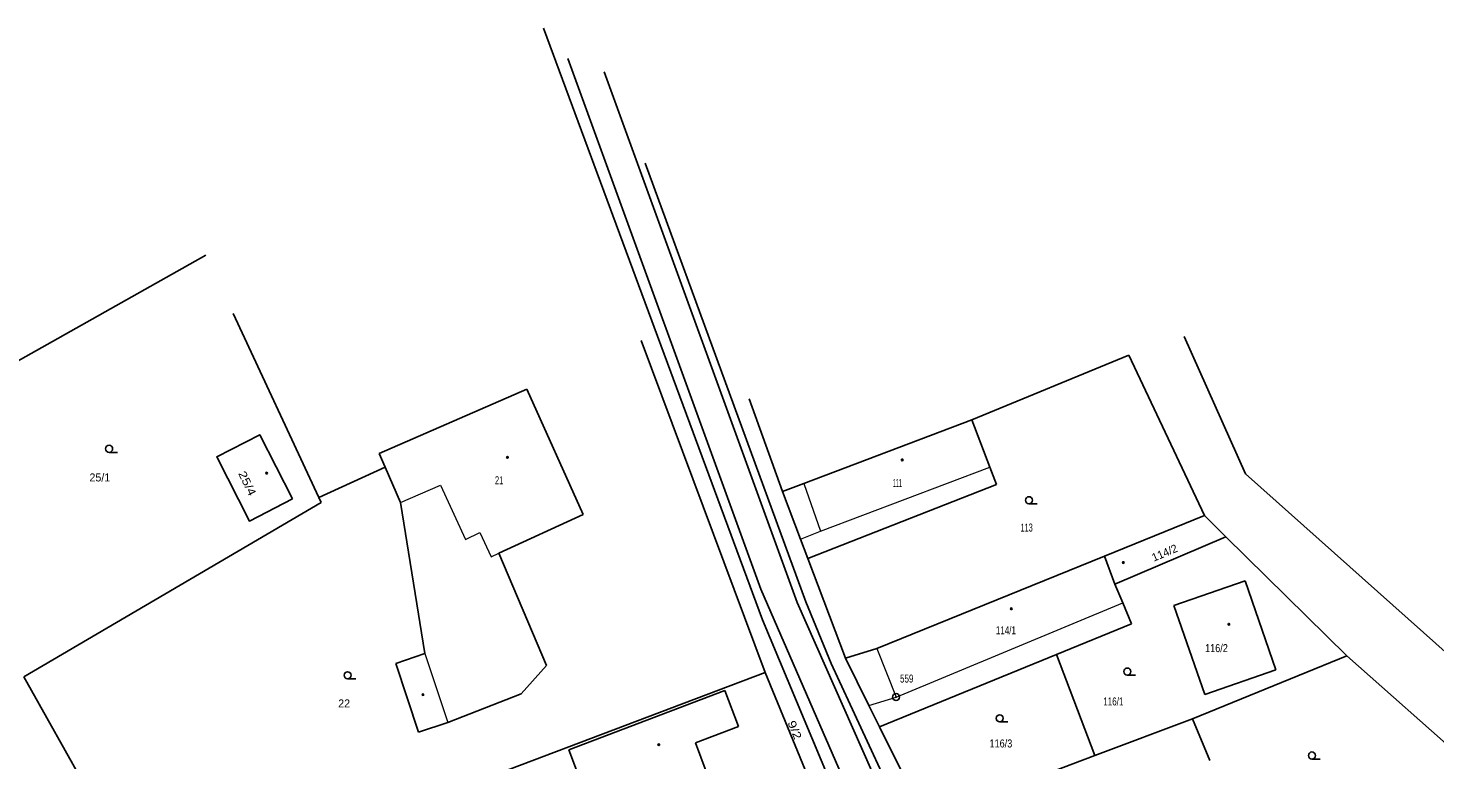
# Model space of a CAD drawing. Extents: x -592965 to -592390, y -1145071 to -1144631.
# Drawn here: x -592769.5 to -592620.1, y -1144708.7 to -1144631 of the extents above; entities that cross this region are included whole.
import ezdxf
from ezdxf.enums import TextEntityAlignment as Align

# ---------------------------------------------------------------- set-up
doc = ezdxf.new("R2010")
doc.units = 0
doc.header["$LTSCALE"] = 0.17
doc.layers.add('4', color=7, linetype='Continuous', lineweight=25)

msp = doc.modelspace()

# ---------------------------------------------------------------- linework, layer by layer
at = {"layer": '4'}
for p, q in [((-592712.14, -1144634.26), (-592691.66, -1144690.59)), ((-592708.27, -1144635.66), (-592687.79, -1144692.02)), ((-592703.94, -1144645.37), (-592686.85, -1144691.94)), ((-592784.33, -1144674.09), (-592750.58, -1144655.15)), ((-592747.69, -1144661.32), (-592738.57, -1144680.87)), ((-592704.36, -1144664.19), (-592691.2, -1144699.44)), ((-592646.68, -1144663.78), (-592640.18, -1144678.35)), ((-592669.23, -1144672.61), (-592652.56, -1144665.74)), ((-592652.56, -1144665.74), (-592644.54, -1144682.77)), ((-592732.18, -1144676.2), (-592716.5, -1144669.38)), ((-592716.5, -1144669.38), (-592710.51, -1144682.66)), ((-592692.87, -1144670.4), (-592689.34, -1144680.24)), ((-592687.08, -1144679.38), (-592669.23, -1144672.61)), ((-592669.23, -1144672.61), (-592667.32, -1144677.64)), ((-592759.985, -1144676.07), (-592760.86, -1144676.07)), ((-592732.18, -1144676.2), (-592731.54, -1144677.66)), ((-592738.57, -1144680.87), (-592731.54, -1144677.66)), ((-592731.54, -1144677.66), (-592729.92, -1144681.4)), ((-592667.32, -1144677.64), (-592666.62, -1144679.5)), ((-592640.18, -1144678.35), (-592593.65, -1144719.8)), ((-592689.34, -1144680.24), (-592687.08, -1144679.38)), ((-592686.65, -1144687.35), (-592666.62, -1144679.5)), ((-592769.91, -1144699.89), (-592738.34, -1144681.38)), ((-592738.57, -1144680.87), (-592738.34, -1144681.38)), ((-592729.92, -1144681.4), (-592727.32, -1144697.42)), ((-592689.34, -1144680.24), (-592687.43, -1144685.29)), ((-592662.295, -1144681.53), (-592663.17, -1144681.53)), ((-592719.46, -1144686.79), (-592710.51, -1144682.66)), ((-592644.54, -1144682.77), (-592642.26, -1144685.04)), ((-592687.43, -1144685.29), (-592686.65, -1144687.35)), ((-592654.03, -1144690.07), (-592642.26, -1144685.04)), ((-592642.26, -1144685.04), (-592629.42, -1144697.69)), ((-592719.46, -1144686.79), (-592714.4, -1144698.69)), ((-592686.65, -1144687.35), (-592682.65, -1144697.93)), ((-592654.03, -1144690.07), (-592655.14, -1144687.08)), ((-592691.66, -1144690.59), (-592680.91, -1144715.27)), ((-592647.77, -1144692.32), (-592640.2, -1144689.71)), ((-592640.2, -1144689.71), (-592636.94, -1144699.17)), ((-592687.79, -1144692.02), (-592678.19, -1144713.68)), ((-592686.85, -1144691.94), (-592684.18, -1144698.5)), ((-592647.77, -1144692.32), (-592644.49, -1144701.79)), ((-592730.42, -1144698.48), (-592727.32, -1144697.42)), ((-592682.65, -1144697.93), (-592679.33, -1144696.91)), ((-592660.24, -1144697.52), (-592656.17, -1144708.27)), ((-592645.8, -1144704.36), (-592629.42, -1144697.69)), ((-592629.42, -1144697.69), (-592613.93, -1144711.39)), ((-592756.36, -1144724.09), (-592691.2, -1144699.44)), ((-592730.42, -1144698.48), (-592728.01, -1144705.79)), ((-592717.08, -1144701.69), (-592714.4, -1144698.69)), ((-592684.18, -1144698.5), (-592676.33, -1144715.39)), ((-592644.49, -1144701.79), (-592636.94, -1144699.17)), ((-592769.91, -1144699.89), (-592756.36, -1144724.09)), ((-592734.655, -1144700.11), (-592735.53, -1144700.11)), ((-592651.845, -1144699.72), (-592652.72, -1144699.72)), ((-592724.87, -1144704.74), (-592717.08, -1144701.69)), ((-592712.03, -1144707.64), (-592695.45, -1144701.37)), ((-592695.45, -1144701.37), (-592694.02, -1144705.16)), ((-592728.01, -1144705.79), (-592724.87, -1144704.74)), ((-592698.59, -1144706.9), (-592694.02, -1144705.16)), ((-592665.395, -1144704.68), (-592666.27, -1144704.68)), ((-592645.8, -1144704.36), (-592643.94, -1144708.8)), ((-592698.59, -1144706.9), (-592697.44, -1144709.96)), ((-592712.03, -1144707.64), (-592709.92, -1144713.22)), ((-592632.235, -1144708.63), (-592633.11, -1144708.63))]:
    msp.add_line(p, q, dxfattribs=at)
at = {"layer": '4', "lineweight": 13}
for p, q in [((-592685.29, -1144684.43), (-592667.32, -1144677.64)), ((-592729.92, -1144681.4), (-592725.68, -1144679.54)), ((-592687.08, -1144679.38), (-592685.29, -1144684.43)), ((-592687.43, -1144685.29), (-592685.29, -1144684.43)), ((-592677.28, -1144702.05), (-592653.2, -1144692.06)), ((-592727.32, -1144697.42), (-592724.87, -1144704.74)), ((-592679.33, -1144696.91), (-592677.28, -1144702.05)), ((-592680.17, -1144702.93), (-592677.28, -1144702.05))]:
    msp.add_line(p, q, dxfattribs=at)
at = {"layer": '4'}
for points in [[(-592682.6, -1144715), (-592691.47, -1144693.85), (-592714.72, -1144631.04)], [(-592679.33, -1144696.91), (-592655.14, -1144687.08), (-592644.54, -1144682.77)], [(-592654.03, -1144690.07), (-592653.2, -1144692.06), (-592652.28, -1144694.27)], [(-592679.04, -1144705.21), (-592660.24, -1144697.52), (-592652.28, -1144694.27)], [(-592682.65, -1144697.93), (-592680.17, -1144702.93), (-592679.04, -1144705.21), (-592674.05, -1144715.26), (-592669.9, -1144713.45)], [(-592691.2, -1144699.44), (-592685.87, -1144712.37), (-592685.06, -1144715.99), (-592681.65, -1144724.59), (-592678.44, -1144732.7)], [(-592669.9, -1144713.45), (-592656.17, -1144708.27), (-592645.8, -1144704.36)]]:
    msp.add_lwpolyline(points, dxfattribs=at)
msp.add_lwpolyline([(-592741.37, -1144681.02), (-592744.86, -1144674.21), (-592749.42, -1144676.53), (-592745.95, -1144683.37)], close=True, dxfattribs=at)
at = {"layer": '4', "lineweight": 13}
for points in [[(-592725.68, -1144679.54), (-592723.01, -1144685.31), (-592721.47, -1144684.57)], [(-592721.47, -1144684.57), (-592720.27, -1144687.17), (-592719.46, -1144686.79)]]:
    msp.add_lwpolyline(points, dxfattribs=at)
at = {"layer": '4'}
for centre, radius in [((-592760.86, -1144675.695), 0.375), ((-592718.55, -1144676.6), 0.0875), ((-592676.63, -1144676.87), 0.0875), ((-592744.12, -1144678.28), 0.0875), ((-592663.17, -1144681.155), 0.375), ((-592653.14, -1144687.77), 0.0875), ((-592665.03, -1144692.68), 0.0875), ((-592641.93, -1144694.32), 0.0875), ((-592735.53, -1144699.735), 0.375), ((-592652.72, -1144699.345), 0.375), ((-592727.52, -1144701.79), 0.0875), ((-592677.28, -1144702.05), 0.375), ((-592677.28, -1144702.05), 0.0164), ((-592666.27, -1144704.305), 0.375), ((-592702.48, -1144707.1), 0.0875), ((-592633.11, -1144708.255), 0.375)]:
    msp.add_circle(centre, radius, dxfattribs=at)

# ---------------------------------------------------------------- texts
for s, p in [('25/1', (-592762.95, -1144679.16)), ('22', (-592736.53, -1144703.15))]:
    msp.add_text(s, height=0.85, dxfattribs=at).set_placement(p)
for s, rotation, width, p in [('25/4', 295.935, 1.25, (-592747.173, -1144678.304)), ('9/2', 292.402, 1.3, (-592688.828, -1144704.752))]:
    msp.add_text(s, height=0.85, rotation=rotation, dxfattribs=dict(at, width=width)).set_placement(p)
for s, width, p in [('21', 0.7, (-592719.88, -1144679.46)), ('111', 0.4, (-592677.62, -1144679.74)), ('113', 0.6, (-592664.06, -1144684.48)), ('114/1', 0.75, (-592666.684, -1144695.39)), ('116/2', 0.85, (-592644.46, -1144697.28)), ('116/1', 0.75, (-592655.27, -1144702.94)), ('116/3', 0.85, (-592667.356, -1144707.4))]:
    msp.add_text(s, height=0.85, dxfattribs=dict(at, width=width)).set_placement(p)
msp.add_text('114/2', height=0.85, rotation=23.14, dxfattribs=at).set_placement((-592649.9, -1144687.687))
at = {"layer": '4', "width": 0.75}
msp.add_text('559', height=0.85, dxfattribs=at).set_placement((-592676.15, -1144700.51), align=Align.CENTER)

doc.saveas('drawing.dxf')
